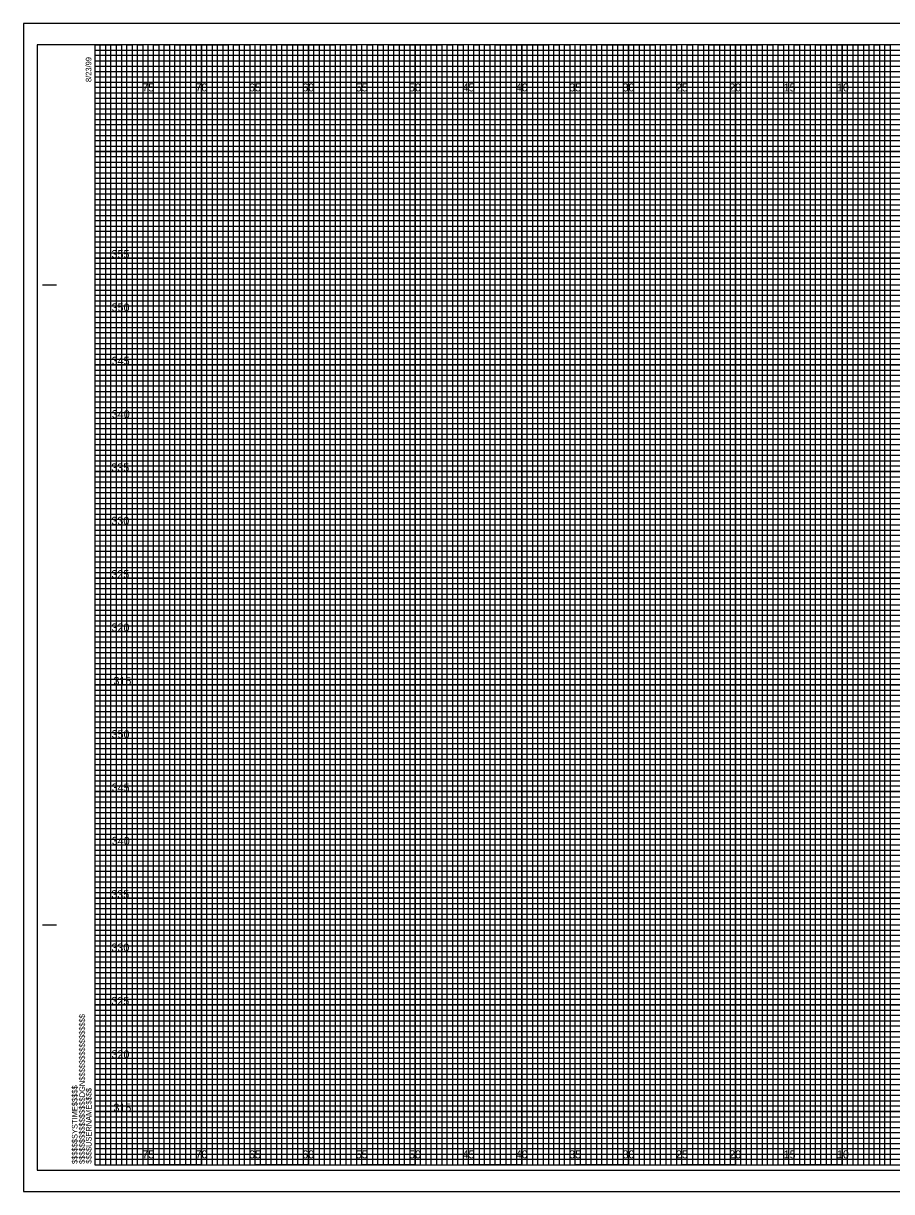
# Model space of a CAD drawing. Extents: x -7 to 162, y -2 to 327.
# Drawn here: x -6.7 to 74.6, y -2.5 to 107 of the extents above; entities that cross this region are included whole.
import ezdxf

# ---------------------------------------------------------------- set-up
doc = ezdxf.new("R2010")
doc.units = 0
for name, color, linetype in [('Exist Cross Section Cell', 7, 'Continuous'), ('Exist XS Center Line Elevation Label', 7, 'Continuous'), ('Exist XS Ground Line', 7, 'Continuous'), ('Old_Level_1', 7, 'Continuous'), ('Prop XS Bridge', 7, 'Continuous'), ('Prop XS Ditch Standard Text', 7, 'Continuous'), ('Prop XS EOT Tick Mark', 7, 'Continuous'), ('Prop XS Finish Grade Earthwork', 7, 'Continuous'), ('Prop XS Label Text', 7, 'Continuous'), ('Prop XS Subgrade', 7, 'Continuous'), ('Scratch_Level_3', 7, 'Continuous')]:
    doc.layers.add(name, color=color, linetype=linetype)

msp = doc.modelspace()

# ---------------------------------------------------------------- linework, layer by layer
at = {"layer": 'Exist XS Center Line Elevation Label'}
for points in [[(0, 105), (2.5, 105), (2.5, 0), (7.5, 0), (7.5, 105), (12.5, 105), (12.5, 0), (17.5, 0), (17.5, 105), (22.5, 105), (22.5, 0), (27.5, 0), (27.5, 105), (32.5, 105), (32.5, 0), (37.5, 0), (37.5, 105), (42.5, 105), (42.5, 0), (47.5, 0), (47.5, 105), (52.5, 105), (52.5, 0), (57.5, 0), (57.5, 105), (62.5, 105), (62.5, 0), (67.5, 0), (67.5, 105), (72.5, 105), (72.5, 0), (77.5, 0)], [(0, 102.5), (137.5, 102.5)], [(0, 92.5), (160, 92.5), (160, 97.5), (0, 97.5)], [(0, 82.5), (160, 82.5), (160, 87.5), (0, 87.5)], [(0, 72.5), (160, 72.5), (160, 77.5), (0, 77.5)], [(0, 62.5), (160, 62.5), (160, 67.5), (0, 67.5)], [(0, 52.5), (160, 52.5), (160, 57.5), (0, 57.5)], [(0, 42.5), (160, 42.5), (160, 47.5), (0, 47.5)], [(0, 32.5), (160, 32.5), (160, 37.5), (0, 37.5)], [(0, 22.5), (160, 22.5), (160, 27.5), (0, 27.5)], [(0, 12.5), (160, 12.5), (160, 17.5), (0, 17.5)], [(0, 2.5), (160, 2.5), (160, 7.5), (0, 7.5)]]:
    msp.add_lwpolyline(points, dxfattribs=at)
at = {"layer": 'Exist XS Ground Line'}
for p, q in [((5, 105), (0, 105)), ((5, 0), (5, 105)), ((15, 105), (10, 105)), ((10, 105), (10, 0)), ((15, 0), (15, 105)), ((25, 105), (20, 105)), ((20, 105), (20, 0)), ((25, 0), (25, 105)), ((35, 105), (30, 105)), ((30, 105), (30, 0)), ((35, 0), (35, 105)), ((45, 105), (40, 105)), ((40, 105), (40, 0)), ((45, 0), (45, 105)), ((55, 105), (50, 105)), ((50, 105), (50, 0)), ((55, 0), (55, 105)), ((65, 105), (60, 105)), ((60, 105), (60, 0)), ((65, 0), (65, 105)), ((75, 105), (70, 105)), ((70, 105), (70, 0)), ((10, 0), (5, 0)), ((20, 0), (15, 0)), ((30, 0), (25, 0)), ((40, 0), (35, 0)), ((50, 0), (45, 0)), ((60, 0), (55, 0)), ((70, 0), (65, 0))]:
    msp.add_line(p, q, dxfattribs=at)
for points in [[(0, 100), (160, 100), (160, 95), (0, 95)], [(0, 90), (160, 90), (160, 85), (0, 85)], [(0, 80), (160, 80), (160, 75), (0, 75)], [(0, 70), (160, 70), (160, 65), (0, 65)], [(0, 60), (160, 60), (160, 55), (0, 55)], [(0, 50), (160, 50), (160, 45), (0, 45)], [(0, 40), (160, 40), (160, 35), (0, 35)], [(0, 30), (160, 30), (160, 25), (0, 25)], [(0, 20), (160, 20), (160, 15), (0, 15)], [(0, 10), (160, 10), (160, 5), (0, 5)]]:
    msp.add_lwpolyline(points, dxfattribs=at)
at = {"layer": 'Old_Level_1'}
msp.add_lwpolyline([(-5.4, -0.5), (161.2, -0.5), (161.2, 105), (-5.4, 105)], close=True, dxfattribs=at)
at = {"layer": 'Prop XS Bridge'}
for p, q in [((5, 0), (5, 105)), ((10, 0), (10, 105)), ((15, 0), (15, 105)), ((20, 0), (20, 105)), ((25, 0), (25, 105)), ((30, 0), (30, 105)), ((35, 0), (35, 105)), ((40, 0), (40, 105)), ((45, 0), (45, 105)), ((50, 0), (50, 105)), ((55, 0), (55, 105)), ((60, 0), (60, 105)), ((65, 0), (65, 105)), ((70, 0), (70, 105)), ((0, 100), (160, 100)), ((0, 95), (160, 95)), ((0, 90), (160, 90)), ((0, 85), (160, 85)), ((0, 80), (160, 80)), ((0, 75), (160, 75)), ((0, 70), (160, 70)), ((0, 65), (160, 65)), ((0, 60), (160, 60)), ((0, 55), (160, 55)), ((0, 50), (160, 50)), ((0, 45), (160, 45)), ((0, 40), (160, 40)), ((0, 35), (160, 35)), ((0, 30), (160, 30)), ((0, 25), (160, 25)), ((0, 20), (160, 20)), ((0, 15), (160, 15)), ((0, 10), (160, 10)), ((0, 5), (160, 5))]:
    msp.add_line(p, q, dxfattribs=at)
at = {"layer": 'Prop XS EOT Tick Mark'}
for p, q in [((-4.9, 82.5), (-3.65, 82.5)), ((-4.85, 82.5), (-3.6, 82.5)), ((-4.9, 22.5), (-3.65, 22.5)), ((-4.85, 22.5), (-3.6, 22.5)), ((0, 0), (0, 0)), ((0, 0), (0, 0)), ((0, 0), (0, 0)), ((0, 0), (0, 0)), ((0, 0), (0, 0)), ((0, 0), (0, 0)), ((0, 0), (0, 0))]:
    msp.add_line(p, q, dxfattribs=at)
msp.add_lwpolyline([(160, 105), (0, 105), (0, 0), (160, 0)], close=True, dxfattribs=at)
at = {"layer": 'Prop XS Finish Grade Earthwork'}
for p, q in [((161.65, 107), (-6.7, 107)), ((-6.7, 107), (-6.7, -2.5)), ((-6.7, -2.5), (161.65, -2.5))]:
    msp.add_line(p, q, dxfattribs=at)
at = {"layer": 'Prop XS Label Text'}
for points in [[(0, 0), (0.5, 0), (0.5, 105), (1, 105), (1, 0)], [(1, 0), (1.5, 0), (1.5, 105), (2, 105), (2, 0)], [(2.5, 0), (3, 0), (3, 105), (3.5, 105), (3.5, 0)], [(3.5, 0), (4, 0), (4, 105), (4.5, 105), (4.5, 0)], [(5, 0), (5.5, 0), (5.5, 105), (6, 105), (6, 0)], [(6, 0), (6.5, 0), (6.5, 105), (7, 105), (7, 0)], [(7.5, 0), (8, 0), (8, 105), (8.5, 105), (8.5, 0)], [(8.5, 0), (9, 0), (9, 105), (9.5, 105), (9.5, 0)], [(10, 0), (10.5, 0), (10.5, 105), (11, 105), (11, 0)], [(11, 0), (11.5, 0), (11.5, 105), (12, 105), (12, 0)], [(12.5, 0), (13, 0), (13, 105), (13.5, 105), (13.5, 0)], [(13.5, 0), (14, 0), (14, 105), (14.5, 105), (14.5, 0)], [(15, 0), (15.5, 0), (15.5, 105), (16, 105), (16, 0)], [(16, 0), (16.5, 0), (16.5, 105), (17, 105), (17, 0)], [(17.5, 0), (18, 0), (18, 105), (18.5, 105), (18.5, 0)], [(18.5, 0), (19, 0), (19, 105), (19.5, 105), (19.5, 0)], [(20, 0), (20.5, 0), (20.5, 105), (21, 105), (21, 0)], [(21, 0), (21.5, 0), (21.5, 105), (22, 105), (22, 0)], [(22.5, 0), (23, 0), (23, 105), (23.5, 105), (23.5, 0)], [(23.5, 0), (24, 0), (24, 105), (24.5, 105), (24.5, 0)], [(25, 0), (25.5, 0), (25.5, 105), (26, 105), (26, 0)], [(26, 0), (26.5, 0), (26.5, 105), (27, 105), (27, 0)], [(27.5, 0), (28, 0), (28, 105), (28.5, 105), (28.5, 0)], [(28.5, 0), (29, 0), (29, 105), (29.5, 105), (29.5, 0)], [(30, 0), (30.5, 0), (30.5, 105), (31, 105), (31, 0)], [(31, 0), (31.5, 0), (31.5, 105), (32, 105), (32, 0)], [(32.5, 0), (33, 0), (33, 105), (33.5, 105), (33.5, 0)], [(33.5, 0), (34, 0), (34, 105), (34.5, 105), (34.5, 0)], [(35, 0), (35.5, 0), (35.5, 105), (36, 105), (36, 0)], [(36, 0), (36.5, 0), (36.5, 105), (37, 105), (37, 0)], [(37.5, 0), (38, 0), (38, 105), (38.5, 105), (38.5, 0)], [(38.5, 0), (39, 0), (39, 105), (39.5, 105), (39.5, 0)], [(40, 0), (40.5, 0), (40.5, 105), (41, 105), (41, 0)], [(41, 0), (41.5, 0), (41.5, 105), (42, 105), (42, 0)], [(42.5, 0), (43, 0), (43, 105), (43.5, 105), (43.5, 0)], [(43.5, 0), (44, 0), (44, 105), (44.5, 105), (44.5, 0)], [(45, 0), (45.5, 0), (45.5, 105), (46, 105), (46, 0)], [(46, 0), (46.5, 0), (46.5, 105), (47, 105), (47, 0)], [(47.5, 0), (48, 0), (48, 105), (48.5, 105), (48.5, 0)], [(48.5, 0), (49, 0), (49, 105), (49.5, 105), (49.5, 0)], [(50, 0), (50.5, 0), (50.5, 105), (51, 105), (51, 0)], [(51, 0), (51.5, 0), (51.5, 105), (52, 105), (52, 0)], [(52.5, 0), (53, 0), (53, 105), (53.5, 105), (53.5, 0)], [(53.5, 0), (54, 0), (54, 105), (54.5, 105), (54.5, 0)], [(55, 0), (55.5, 0), (55.5, 105), (56, 105), (56, 0)], [(56, 0), (56.5, 0), (56.5, 105), (57, 105), (57, 0)], [(57.5, 0), (58, 0), (58, 105), (58.5, 105), (58.5, 0)], [(58.5, 0), (59, 0), (59, 105), (59.5, 105), (59.5, 0)], [(60, 0), (60.5, 0), (60.5, 105), (61, 105), (61, 0)], [(61, 0), (61.5, 0), (61.5, 105), (62, 105), (62, 0)], [(62.5, 0), (63, 0), (63, 105), (63.5, 105), (63.5, 0)], [(63.5, 0), (64, 0), (64, 105), (64.5, 105), (64.5, 0)], [(65, 0), (65.5, 0), (65.5, 105), (66, 105), (66, 0)], [(66, 0), (66.5, 0), (66.5, 105), (67, 105), (67, 0)], [(67.5, 0), (68, 0), (68, 105), (68.5, 105), (68.5, 0)], [(68.5, 0), (69, 0), (69, 105), (69.5, 105), (69.5, 0)], [(70, 0), (70.5, 0), (70.5, 105), (71, 105), (71, 0)], [(71, 0), (71.5, 0), (71.5, 105), (72, 105), (72, 0)], [(72.5, 0), (73, 0), (73, 105), (73.5, 105), (73.5, 0)], [(73.5, 0), (74, 0), (74, 105), (74.5, 105), (74.5, 0)]]:
    msp.add_lwpolyline(points, dxfattribs=at)
at = {"layer": 'Prop XS Subgrade'}
msp.add_lwpolyline([(-6.7, -2.5), (161.65, -2.5), (161.65, 107), (-6.7, 107)], close=True, dxfattribs=at)
at = {"layer": 'Scratch_Level_3'}
for p, q in [((0, 104.5), (130, 104.5)), ((130, 103.99), (0, 103.99)), ((0, 103.99), (0, 103.5)), ((0, 103.5), (130, 103.5)), ((130, 102.95), (0, 102.95)), ((0, 102.95), (0, 102)), ((0, 102), (160, 102))]:
    msp.add_line(p, q, dxfattribs=at)
for points in [[(0, 101.5), (135, 101.5), (160, 101.5), (160, 101), (0, 101)], [(0, 100.5), (160, 100.5), (160, 99.5), (0, 99.5)], [(0, 99), (160, 99), (160, 98.5), (0, 98.49)], [(0, 98), (160, 98), (160, 97), (0, 97)], [(0, 96.5), (160, 96.5), (160, 96), (0, 96)], [(0, 95.5), (160, 95.5), (160, 94.5), (0, 94.5)], [(0, 94), (160, 94), (160, 93.5), (0, 93.5)], [(0, 93), (160, 93), (160, 92), (0, 92)], [(0, 91.5), (160, 91.5), (160, 91), (0, 91)], [(0, 90.5), (160, 90.5), (160, 89.5), (0, 89.5)], [(0, 89), (160, 89), (160, 88.5), (0, 88.5)], [(0, 88), (160, 88), (160, 86.98), (160, 86.5), (160, 86), (0, 86)], [(0, 87), (160, 87), (160, 86.5), (0, 86.5)], [(0, 85.5), (160, 85.5), (160, 84.5), (0, 84.52)], [(0, 84.52), (160, 84.5), (160, 84), (0, 84)], [(0, 83.5), (160, 83.5), (160, 83), (0, 83)], [(0, 82), (160, 82), (160, 81.5), (0, 81.5)], [(0, 81), (160, 81), (160, 80.5), (0, 80.5)], [(-0.04, 79.45), (160, 79.45), (160, 78.94), (-0.04, 78.94)], [(0, 78.5), (160, 78.5), (160, 78), (0, 78)], [(0, 77), (160, 77), (160, 76.5), (0, 76.5)], [(0, 76), (160, 76), (160, 75.5), (0, 75.5)], [(0, 74.5), (160, 74.5), (160, 74), (0, 74)], [(0, 73.5), (160, 73.5), (160, 73), (0, 73)], [(0, 72), (160, 72), (160, 71.5), (0, 71.5)], [(0, 71), (160, 71), (160, 70.5), (0, 70.5)], [(0, 69.5), (160, 69.5), (160, 68.99), (0, 69)], [(0, 68.5), (160, 68.5), (160, 68), (0, 68)], [(0, 67), (160, 67), (160, 66.5), (0, 66.5)], [(0, 66), (160, 66), (160, 65.5), (0, 65.5)], [(0, 64.5), (160, 64.5), (160, 64), (0, 64)], [(0, 63.5), (160, 63.5), (160, 63), (0, 63)], [(0, 62), (160, 62), (160, 61.5), (0, 61.5)], [(0, 61), (160, 61), (160, 60.5), (0, 60.5)], [(0, 59.5), (160, 59.5), (160, 59), (0, 59)], [(0, 58.5), (160.03, 58.45), (160, 58), (0, 58)], [(0, 57), (160, 57), (160, 56.5), (0, 56.5)], [(0, 56), (160, 56), (160, 55.5), (0, 55.5)], [(0, 54.5), (160, 54.5), (160, 54), (0, 54)], [(0, 53.5), (160, 53.5), (160, 53), (0, 53)], [(0, 52), (160, 52), (160, 51.5), (0, 51.5)], [(0, 51), (160, 51), (160, 50.5), (0, 50.5)], [(0, 49.5), (160, 49.5), (160, 49), (0, 49)], [(0, 48.5), (160, 48.5), (160, 48), (0, 48)], [(0, 47), (160, 47), (160, 46.5), (0, 46.5)], [(0, 46), (160, 46), (160, 45.5), (0, 45.5)], [(0, 44.5), (160, 44.5), (160, 44), (0, 44)], [(0, 43.5), (160, 43.5), (160, 43), (0, 43)], [(0, 42), (160, 42), (160, 41.5), (0, 41.5)], [(0, 41), (160, 41), (160, 40.5), (0, 40.5)], [(0, 39.5), (160, 39.5), (160, 38.99), (0, 39)], [(0, 38.5), (160, 38.5), (160, 38), (0, 38)], [(0, 37), (160, 37), (160, 36.5), (0, 36.5)], [(0, 36), (160, 36), (160, 35.5), (0, 35.5)], [(0, 34.5), (160, 34.5), (160, 34), (0, 34)], [(0, 33.5), (160, 33.5), (160, 33), (0, 33)], [(0, 32), (160, 32), (160, 31.5), (0, 31.5)], [(0, 31), (160, 31), (160, 30.5), (0, 30.5)], [(0, 29.5), (160, 29.5), (160, 29), (0, 29)], [(0, 28.5), (160.03, 28.46), (160, 28), (0, 28)], [(0, 27), (160, 27), (160, 26.5), (0, 26.5)], [(0, 26), (160, 26), (160, 25.5), (0, 25.5)], [(0, 24.5), (160, 24.5), (160, 24), (0, 24)], [(0, 23.5), (160, 23.5), (160, 23), (0, 23)], [(0, 22), (160, 22), (160, 21.5), (0, 21.5)], [(0, 21), (160, 21), (160, 20.5), (0, 20.5)], [(0, 19.5), (160, 19.5), (160, 19), (0, 19)], [(0, 18.5), (160, 18.5), (160, 18), (0, 18)], [(0, 17), (160, 17), (160, 16.5), (0, 16.5)], [(0, 16), (160, 16), (160, 15.5), (0, 15.5)], [(0, 14.5), (160, 14.5), (160, 14), (0, 14)], [(0, 13.5), (160, 13.5), (160, 13), (0, 13)], [(0, 12), (160, 12), (160, 11.5), (0, 11.5)], [(0, 11), (160, 11), (160, 10.5), (0, 10.5)], [(0, 9.5), (160, 9.5), (160, 9), (0, 9)], [(0, 8.5), (160, 8.5), (160, 8), (0, 8)], [(0, 7), (160, 7), (160, 6.5), (0, 6.5)], [(0, 6), (160, 6), (160, 5.5), (0, 5.5)], [(0, 4.5), (160, 4.5), (160, 4), (0, 4)], [(0, 3.5), (160, 3.5), (160, 3), (0, 3)], [(0, 2), (160, 2), (160, 1.5), (0, 1.5)], [(0, 1), (160, 1), (160, 0.5), (0, 0.5)]]:
    msp.add_lwpolyline(points, dxfattribs=at)

# ---------------------------------------------------------------- texts
at = {"layer": 'Exist Cross Section Cell'}
for s, p in [('75', (4.44, 100.62)), ('70', (9.43, 100.62)), ('65', (14.44, 100.62)), ('60', (19.43, 100.62)), ('55', (24.44, 100.62)), ('50', (29.43, 100.62)), ('45', (34.44, 100.62)), ('40', (39.43, 100.62)), ('35', (44.44, 100.62)), ('30', (49.43, 100.62)), ('25', (54.44, 100.62)), ('20', (59.43, 100.62)), ('15', (64.53, 100.62)), ('10', (69.52, 100.62)), ('75', (4.44, 0.62)), ('70', (9.43, 0.62)), ('65', (14.44, 0.62)), ('60', (19.43, 0.62)), ('55', (24.44, 0.62)), ('50', (29.43, 0.62)), ('45', (34.44, 0.62)), ('40', (39.43, 0.62)), ('35', (44.44, 0.62)), ('30', (49.43, 0.62)), ('25', (54.44, 0.62)), ('20', (59.43, 0.62)), ('15', (64.53, 0.62)), ('10', (69.52, 0.62))]:
    msp.add_text(s, height=0.75, dxfattribs=at).set_placement(p)
at = {"layer": 'Prop XS Ditch Standard Text'}
for s, p in [('355', (1.56, 85)), ('350', (1.57, 80)), ('345', (1.58, 75)), ('340', (1.59, 70)), ('335', (1.54, 65)), ('330', (1.55, 60)), ('325', (1.55, 55)), ('320', (1.56, 50)), ('315', (1.74, 45)), ('350', (1.57, 40)), ('345', (1.58, 35)), ('340', (1.59, 30)), ('335', (1.54, 25)), ('330', (1.55, 20)), ('325', (1.55, 15)), ('320', (1.56, 10)), ('315', (1.74, 5))]:
    msp.add_text(s, height=0.75, dxfattribs=at).set_placement(p)
at = {"layer": 'Prop XS EOT Tick Mark'}
for s, p in [('8/23/99', (-0.33, 101.5)), ('$$$$$$$$$$$$$$$$DGN$$$$$$$$$$$$$$$$', (-0.94, 0.09)), ('$$$$$$SYSTIME$$$$$', (-1.63, 0.09)), ('$$$$USERNAME$$$$', (-0.31, 0.12))]:
    msp.add_text(s, height=0.525, rotation=90, dxfattribs=at).set_placement(p)

doc.saveas('drawing.dxf')
